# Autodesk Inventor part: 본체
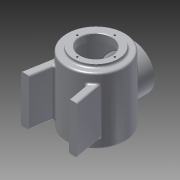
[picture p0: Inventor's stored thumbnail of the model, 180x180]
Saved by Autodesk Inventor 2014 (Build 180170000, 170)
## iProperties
Created: 2015-01
Part Number: 본체
Material: 알루미늄 6061
Document SubType Name: Modeling
Designer: Administrator
Density: 2.71 g/cm^3
Appearance: 알루미늄 - 평지
Mass: 1021.13 g
Surface Area: 1060.37 cm^2
Volume: 376.8 cm^3
Author: Administrator
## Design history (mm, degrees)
sketch "스케치1"
  geometry: L1 (-34, -80)-(-27.282, -41.901); L2 (-48, -80)-(-39.336, -30.865); L3 (-48, -80)-(-34, -80); L4 (0, 50)-(0, -50); A1 r 50 centre (0, 0) between (0, 50) and (-39.336, -30.865); A2 r 50 centre (0, 0) between (-27.282, -41.901) and (0, -50); 1 further point
  constraints: 8 end point, 4 point on circle, 2 centre point, 1 coincident, 1 horizontal, 1 parallel, 1 perpendicular
  dimensions: "d8" = 50 radius of A2; "d9" = 50 radius of A1; "d12" = 13.78731 distance between parallel lines of L1 L2; "d15" = 19.59161 distance from line of point (0, 0) L1; "d16" = 80 distance from line of point (0, 0) L3; "d33" = 10 deg angle of L4 L1; "d34" = 0 distance from line of point (0, 0) L4
extrude "돌출1" new body sketch "스케치1" distance "d17" = 40; taper "d18" = 0 deg
sketch "스케치7"
  geometry: L1 (0, -50)-(0, 50) reference; L2 (0, 50)-(0, -50); A1 r 50 centre (0, 0) between (0, 50) and (-39.336, -30.865) reference; A2 r 50 centre (0, 0) between (0, 50) and (0, -50)
  constraints: 2 end point, 2 point on circle, 1 centre point, 1 coincident, 1 collinear
extrude "돌출6" join sketch "스케치7" distance "d36" = 16; taper "d37" = 0 deg
sketch "스케치8"
  geometry: L1 (-34, 30)-(-34, 130) reference; A1 r 50 centre (-34, 80) between (-34, 30) and (-34, 130) reference
extrude "돌출7" join sketch "스케치8" distance "d38" = 16; taper "d39" = 0 deg
sketch "스케치9"
  geometry: L1 (0, -50)-(0, 50) reference; A1 r 50 centre (0, 0) between (0, 50) and (0, -50) reference; A2 r 38 centre (0, 0) between (0, 38) and (0, -38)
  constraints: 2 point on circle, 2 point on line, 1 centre point, 1 coincident
  dimensions: "d40" = 76 diameter of A2
extrude "돌출8" join sketch "스케치9" distance "d41" = 5; taper "d42" = 0 deg
sketch "스케치10"
  geometry: L1 (-34, 42)-(-34, 118) reference; A1 r 38 centre (-34, 80) between (-34, 42) and (-34, 118) reference
extrude "돌출9" join sketch "스케치10" distance "d43" = 5; taper "d44" = 0 deg
sketch "스케치11"
  geometry: L1 (30, -44)-(84, -44); L2 (30, -56)-(84, -56); L3 (84, -44)-(84, -56); L4 (30, -44)-(30, -56); 1 further point
  constraints: 8 end point
  dimensions: "d46" = 54 distance between parallel lines of L3 L4; "d48" = 12 distance between parallel lines of L2 L1
extrude "돌출10" join sketch "스케치11" distance "d50" = 52; taper "d51" = 0 deg
sketch "스케치12"
  geometry: C1 r 38 at (0, 1); 2 further points
  constraints: 1 centre point
  dimensions: "d53" = 76 diameter of C1
extrude "돌출11" join sketch "스케치12" distance "d54" = 62; taper "d55" = 0 deg
sketch "스케치13"
  geometry: C1 r 38 at (0, 0) reference; C2 r 27 at (0, 0)
  constraints: 1 centre point, 1 coincident
  dimensions: "d56" = 54 diameter of C2
extrude "돌출12" cut sketch "스케치13" distance "d57" = 12; taper "d58" = 0 deg
sketch "스케치14"
  geometry: C1 r 38 at (0, 0) reference; C2 r 27 at (0, 0)
  constraints: 1 centre point, 1 coincident
  dimensions: "d59" = 54 diameter of C2
extrude "돌출13" cut sketch "스케치14" distance "d60" = 13; taper "d61" = 0 deg
sketch "스케치15"
  geometry: C1 r 27 at (0, 0) reference; C2 r 45 at (0, 0)
  constraints: 1 centre point, 1 coincident
  dimensions: "d62" = 90 diameter of C2
extrude "돌출14" cut sketch "스케치15" distance "d63" = 97; taper "d64" = 0 deg
sketch "스케치16"
  geometry: C1 r 5.108 at (0, 32)
  constraints: 1 centre point
hole "구멍1" sketch "스케치16" at (0, 32) diameter "d66" = 3.242; stored, may be unused: countersink angle "d70" = 90 deg, drill point angle "d72" = 118 deg; dims "d67" = 8, "d68" = 4, "d69" = 2, "d71" = 10
sketch "스케치17"
  geometry: C1 r 1.621 at (0, 32) reference
hole "구멍2" sketch "스케치17" at (0, 32) diameter "d76" = 3.242; stored, may be unused: countersink angle "d80" = 90 deg, drill point angle "d82" = 118 deg; dims "d77" = 8, "d78" = 4, "d79" = 2, "d81" = 10
sketch "스케치20"
  geometry: L1 (-80.68, -46.398)-(-30.905, -46.398); L2 (-30.905, -46.398)-(-30.905, -53.602); L3 (-30.905, -53.602)-(-80.68, -53.602); L4 (-80.68, -53.602)-(-80.68, -46.398); 1 further point
  constraints: 2 other
feature "엠보싱1" sketch "스케치20" dims "d8" = 50, "d9" = 50, "d12" = 13.78731, "d15" = 19.59161, "d16" = 80, "d33" = 10 deg, "d34" = 0, "d100" = 0.5, "d101" = 0
chamfer "모따기1" distance "d102" = 1; stored, may be unused: second distance "d103" = 2, angle "d104" = 45 deg
chamfer "모따기2" distance "d105" = 1; stored, may be unused: second distance "d106" = 2, angle "d107" = 45 deg
fillet "모깎기1" dims "d111" = 3
fillet "모깎기2" dims "d112" = 3
fillet "모깎기3" dims "d113" = 3
sketch "스케치22"
  geometry: C1 r 38 at (0, 0) reference; C2 r 27 at (0, 0); 1 further point
  constraints: 1 centre point
  dimensions: "d115" = 54 diameter of C2
extrude "돌출16" cut sketch "스케치22" distance "d116" = 30; taper "d117" = 0 deg
sketch "스케치23"
  geometry: C1 r 2.093 at (0, 32); 1 further point
  constraints: 1 centre point
hole "구멍4" sketch "스케치23" at (0, 32) diameter "d119" = 3.242; stored, may be unused: countersink angle "d123" = 90 deg, drill point angle "d125" = 118 deg; dims "d120" = 8, "d121" = 4, "d122" = 2, "d124" = 10
chamfer "모따기4" distance "d129" = 1; stored, may be unused: second distance "d130" = 2, angle "d131" = 45 deg
fillet "모깎기4" dims "d132" = 3
node "솔리드1"
mirror "대칭2"
mirror "대칭3"
pattern_circular "원형 패턴1" dims angle "d74" = 360 deg
pattern_circular "원형 패턴2" dims angle "d84" = 360 deg
pattern_circular "원형 패턴4" dims angle "d127" = 360 deg
node "투영된 루프2"
node "투영된 루프3"
